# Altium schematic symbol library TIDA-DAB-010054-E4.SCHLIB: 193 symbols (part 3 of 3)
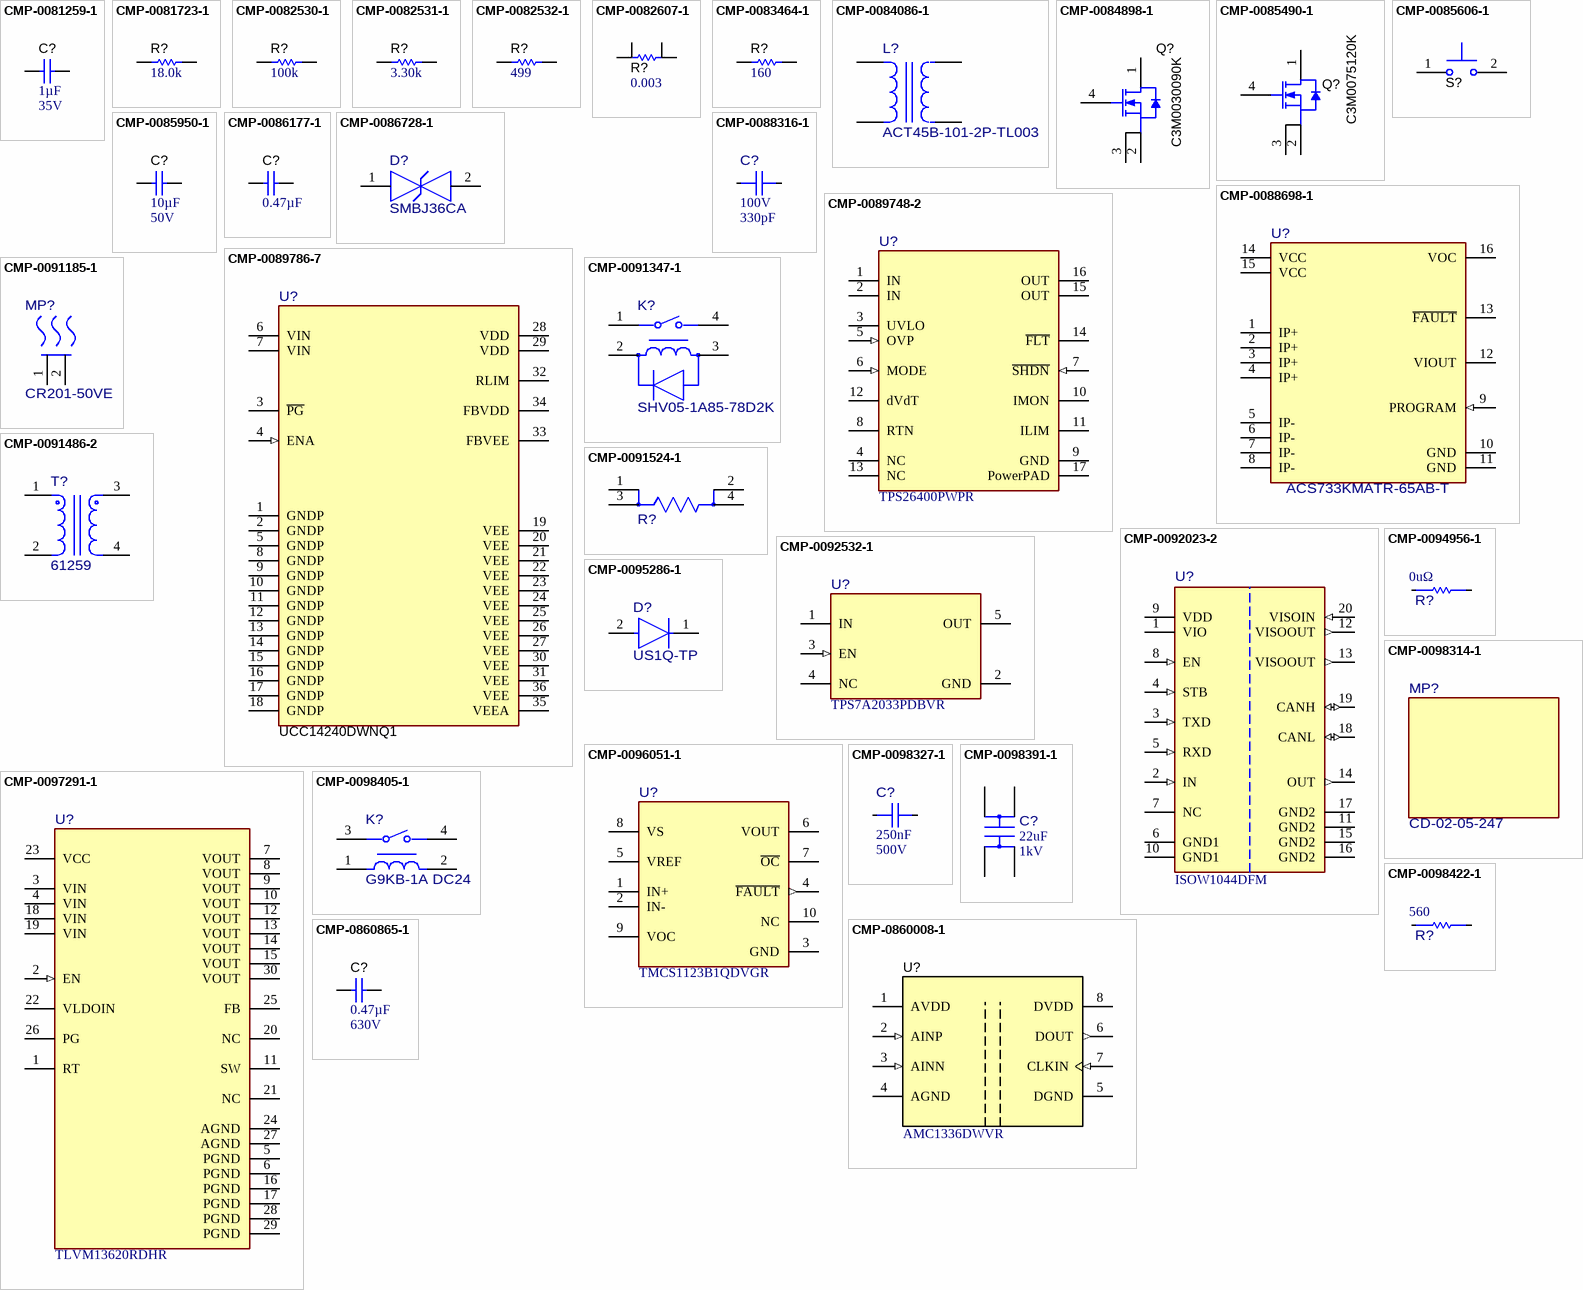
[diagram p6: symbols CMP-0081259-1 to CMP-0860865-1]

## CMP-0092532-1
designator U?, comment TPS7A2033PDBVR
300-mA, Ultra-Low-Noise, Low-IQ, High PSRR LDO; Manufacturer: Texas Instruments; TJmax_C: +125°C; Min Supply Voltage: 1.6V; SizeZ_mm: 1.45mm; Output Voltage: 3.3V; Number Of Outputs: 1; Nominal Supply Current: 6.5uA; AEC Qualified: No; Accuracy Percentage: 1.5%; Max Supply Voltage: 6V; Dropout Voltage: 145mV; Standoff Height: 0mm; Output Type: Fixed
footprint DBV0005A-MFG
footprint DBV0005A-IPC_C
footprint DBV0005A-IPC_B
footprint DBV0005A-IPC_A
pins: 1 IN (power), 2 GND (power), 3 EN (in), 4 NC, 5 OUT

## CMP-0094956-1
designator R?, comment value 0uΩ  (hidden comment: CR0603-10W-000T)
0 Ohms Jumper 0.1W, 1/10W Chip Resistor 0603 (1608 Metric) - Thick Film; Manufacturer: Venkel; Res_ohm: 0; Power_W: 100mW; SizeZ_mm: 0.55mm; AEC Qualified: No
footprint FP-CR0603-10W-000T_0603-MFG
footprint FP-CR0603-10W-000T_0603-IPC_C
footprint FP-CR0603-10W-000T_0603-IPC_B
footprint FP-CR0603-10W-000T_0603-IPC_A
pins: 1, 2

## CMP-0095286-1
designator D?, comment US1Q-TP
Diode Standard 1200 V 1A Surface Mount DO-214AC (SMA); Manufacturer: MCC; Cap_F: 45pF; Max Surge Forward Current: 30A; SizeZ_mm: 2.44mm; TJmax_C: 150°C; Vr_V: 1.2kV; Peak Reverse Current: 5uA; AEC Qualified: No
footprint FP-US1Q-TP_SMA-MFG
pins: 1 CATHODE, 2 ANODE

## CMP-0096051-1
designator U?, comment TMCS1123B1QDVGR
Manufacturer: Texas Instruments; Standoff Height: 0.1mm; SizeZ_mm: 2.65mm; AEC Qualified: No
footprint DVG0010A-MFG
pins: 1 IN+, 2 IN-, 3 GND (power), 4 ~{FAULT} (out), 5 VREF, 6 VOUT, 7 ~{OC} (oc), 8 VS (power), 9 VOC, 10 NC

## CMP-0097291-1
designator U?, comment TLVM13620RDHR
High-Density, 3-V to 36-V Input, 1-V to 6-V Output, 2-A Power Module With Enhanced HotRod™ QFN Package; Manufacturer: Texas Instruments; AEC Qualified: No; Number Of Outputs: 1; TaMax_C: +105°C; Switching Topology: Buck; Output Voltage: 1-6V; TaMin_C: -40°C; Max Supply Voltage: 36V; TJmax_C: +125°C; Switching Frequency: 200-2200kHz; Min Supply Voltage: 3V; SizeZ_mm: 1.9mm; Nominal Supply Current: 4uA; Standoff Height: 0mm; Output Type: AdjustableProgrammable
footprint RDH0030A-MFG
pins: 1 RT, 2 EN (in), 3 VIN (power), 4 VIN (power), 5 PGND (power), 6 PGND (power), 7 VOUT, 8 VOUT, 9 VOUT, 10 VOUT, 11 SW, 12 VOUT (power), 13 VOUT (power), 14 VOUT (power), 15 VOUT (power), 16 PGND (power), 17 PGND (power), 18 VIN (power), 19 VIN (power), 20 NC, 21 NC, 22 VLDOIN (power), 23 VCC, 24 AGND (power), 25 FB, 26 PG (oc), 27 AGND (power), 28 PGND (power), 29 PGND (power), 30 VOUT (power)

## CMP-0098314-1
designator MP?, comment CD-02-05-247
CD-02-05 Series 0.95 x 0.75 inch w/ Hole TO-247 Phase Change Thermal Pad; Manufacturer: Wakefield-Vette; Manufacturer: Wakefield; AEC Qualified: No; SizeZ_mm: 0.0033inch
footprint FP-CD-02-05-247_THERM_PAD_24MM13_19MM05-MFG

## CMP-0098327-1
designator C?, comment ValueDisplayed: 250nF  VDC_V: 500V  (hidden comment: B58043E5254M052)
0.25 µF ±20% 500V Ceramic Capacitor 2220 (5750 Metric); Manufacturer: TDK; Manufacturer: TDK EPCOS; AEC Qualified: No; SizeZ_mm: 1.6mm; Value: 250nF
footprint FP-B58043E5254M052_2220-MFG
footprint FP-B58043E5254M052_2220-IPC_C
footprint FP-B58043E5254M052_2220-IPC_B
footprint FP-B58043E5254M052_2220-IPC_A
pins: 1, 2

## CMP-0098391-1
designator C?, comment ValueDisplayed: 22uF  VDC_V: 1kV  (hidden comment: B32716H0226J000)
Metallized Polypropylene Capacitors (MKP/MFP), 22.0uF, 1000 V DC, 33.0mm(W) x 48.0mm(H) x 42.0mm(L); Manufacturer: TDK; Manufacturer: TDK EPCOS; AEC Grade: Grade 2; AEC Qualified: Yes; Cap_F: 22µF; SizeZ_mm: 48mm; Tolerance_%: 5%; Value: 22µF
footprint FP-B32716H0226J000_RADIAL-MFG
pins: 1, 2, 3, 4

## CMP-0098405-1
designator K?, comment G9KB-1A DC24
General Purpose Relay SPST-NO (1 Form A) 50A 24VDC Coil Through Hole; Manufacturer: Omron; Manufacturer Part Number: G9KB1ADC24BYOMZ; Coil Power_W: 575mW; Coil Type: Non-Latching; Coil Voltage_VDC: 24V; SizeZ_mm: 50.5mm; AEC Qualified: No; Coil Resistance: 206Ω; TaMax_C: +85°C; TaMin_C: -40°C
footprint FP-G9KB-1A DC24_PTH_RELAY_50MM0_36MM7-MFG
pins: 1, 2, 3, 4

## CMP-0098422-1
designator R?, comment value 560  (hidden comment: OC1K561E)
560 Ohms ±10% 1.2W Through Hole Resistor Axial High Voltage, Pulse Withstanding Ceramic; Manufacturer: Ohmite; AEC Qualified: No; SizeZ_mm: 0.349inch; TempCo: 0/-800ppm/°C; VDC_V: 370V
footprint FP-OC1K561E_AXIAL-MFG
pins: 1, 2

## CMP-0860008-1
designator U?, comment AMC1336DWVR
AMC1336 Small, High-Precision, Reinforced Isolated Delta-Sigma Modulator With Input Optimized for Voltage Sensing Applications, DWV0008A (SOIC-8); Manufacturer: Texas Instruments; AEC Qualified: N; AEC Category: Q200; SizeY_mm: 5.85; SizeX_mm: 11.5; SizeAreaWB_mm2: 105.975; SizeArea_mm2: 67.275; CompType: IC; SizeZ_mm: 2.8
footprint DWV0008A (SOIC, 8-Leads, Body 5.95x7.6mm (max), Pitch 1.27mm)
pins: 1 AVDD (power), 2 AINP (in), 3 AINN (in), 4 AGND (power), 5 DGND (power), 6 DOUT (out), 7 CLKIN (in), 8 DVDD (power)
1 alternate drawing of the same symbol

## CMP-0860865-1
designator C?, comment ValueDisplayed: 0.47µF  VDC_V: 630V  (hidden comment: CGA9P1X7T2J474M250KC)
CAP, CERM, 0.47 µF, 630 V,+/- 20%, X7T, AEC-Q200 Grade 1, 2220; Manufacturer: TDK; SizeZ_mm: 2.8; SizeY_mm: 5; AEC Qualified: Y; Cap_Case: 2220; Polarized: N; SizeArea_mm2: 28.5; U/M: EA; AEC Grade: 1; AEC Category: Q200; TaMax_C: 125°C; TaMin_C: -55°C; Cap_F: 470nF; SizeAreaWB_mm2: 53.9; SizeX_mm: 5.7; Value: 0.47uF; CompType: Capacitor
footprint 2220_280 (Chip Capacitor, Body 5.7x5.0mm, IPC Medium Density)
footprint 2220_280M (Chip Capacitor, Body 5.7x5.0mm, IPC Low Density)
footprint 2220_280L (Chip Capacitor, Body 5.7x5.0mm, IPC High Density)
pins: 1, 2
